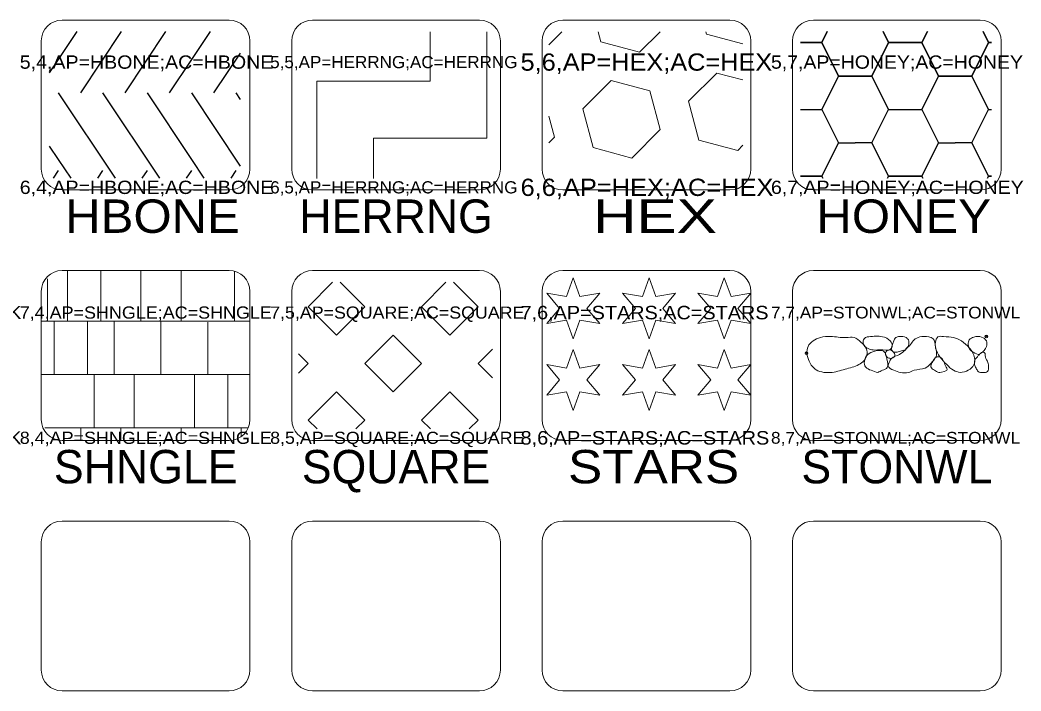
# Model space of a CAD drawing. Extents: x 95935 to 95946.4, y 95971.2 to 95974.7.
# Drawn here: x 95936.835 to 95939.233, y 95971.925 to 95973.532 of the extents above; entities that cross this region are included whole.
import ezdxf
from ezdxf.enums import TextEntityAlignment as Align

# ---------------------------------------------------------------- set-up
doc = ezdxf.new("R2010")
doc.units = 0
doc.header["$LTSCALE"] = 0.013
doc.header["$PDMODE"] = 32
doc.header["$PDSIZE"] = 0.0065
for name, color, linetype, lineweight in [('1', 7, 'Continuous', 13), ('6', 7, 'Continuous', 13), ('63', 7, 'Continuous', 13)]:
    doc.layers.add(name, color=color, linetype=linetype, lineweight=lineweight)
doc.layers.add('20', color=7, linetype='Continuous')

msp = doc.modelspace()

# ---------------------------------------------------------------- linework, layer by layer
at = {"layer": '1'}
for p, q in [((95936.9357, 95973.5318), (95937.3357, 95973.5318)), ((95937.5357, 95973.5318), (95937.9357, 95973.5318)), ((95938.1357, 95973.5318), (95938.5357, 95973.5318)), ((95938.7357, 95973.5318), (95939.1357, 95973.5318)), ((95936.8857, 95973.1747), (95936.8857, 95973.4818)), ((95937.3857, 95973.4818), (95937.3857, 95973.1747)), ((95937.4857, 95973.1747), (95937.4857, 95973.4818)), ((95937.9857, 95973.4818), (95937.9857, 95973.1747)), ((95938.0857, 95973.1747), (95938.0857, 95973.4818)), ((95938.5857, 95973.4818), (95938.5857, 95973.1747)), ((95938.6857, 95973.1747), (95938.6857, 95973.4818)), ((95939.1857, 95973.4818), (95939.1857, 95973.1747)), ((95937.3357, 95973.1247), (95936.9357, 95973.1247)), ((95937.9357, 95973.1247), (95937.5357, 95973.1247)), ((95938.5357, 95973.1247), (95938.1357, 95973.1247)), ((95939.1357, 95973.1247), (95938.7357, 95973.1247)), ((95936.9357, 95972.9318), (95937.3357, 95972.9318)), ((95937.5357, 95972.9318), (95937.9357, 95972.9318)), ((95938.1357, 95972.9318), (95938.5357, 95972.9318)), ((95938.7357, 95972.9318), (95939.1357, 95972.9318)), ((95936.8857, 95972.5747), (95936.8857, 95972.8818)), ((95937.3857, 95972.8818), (95937.3857, 95972.5747)), ((95937.4857, 95972.5747), (95937.4857, 95972.8818)), ((95937.9857, 95972.8818), (95937.9857, 95972.5747)), ((95938.0857, 95972.5747), (95938.0857, 95972.8818)), ((95938.5857, 95972.8818), (95938.5857, 95972.5747)), ((95938.6857, 95972.5747), (95938.6857, 95972.8818)), ((95939.1857, 95972.8818), (95939.1857, 95972.5747)), ((95937.3357, 95972.5247), (95936.9357, 95972.5247)), ((95937.9357, 95972.5247), (95937.5357, 95972.5247)), ((95938.5357, 95972.5247), (95938.1357, 95972.5247)), ((95939.1357, 95972.5247), (95938.7357, 95972.5247)), ((95936.9357, 95972.3318), (95937.3357, 95972.3318)), ((95937.5357, 95972.3318), (95937.9357, 95972.3318)), ((95938.1357, 95972.3318), (95938.5357, 95972.3318)), ((95938.7357, 95972.3318), (95939.1357, 95972.3318)), ((95936.8857, 95971.9747), (95936.8857, 95972.2818)), ((95937.3857, 95972.2818), (95937.3857, 95971.9747)), ((95937.4857, 95971.9747), (95937.4857, 95972.2818)), ((95937.9857, 95972.2818), (95937.9857, 95971.9747)), ((95938.0857, 95971.9747), (95938.0857, 95972.2818)), ((95938.5857, 95972.2818), (95938.5857, 95971.9747)), ((95938.6857, 95971.9747), (95938.6857, 95972.2818)), ((95939.1857, 95972.2818), (95939.1857, 95971.9747)), ((95937.3357, 95971.9247), (95936.9357, 95971.9247)), ((95937.9357, 95971.9247), (95937.5357, 95971.9247)), ((95938.5357, 95971.9247), (95938.1357, 95971.9247)), ((95939.1357, 95971.9247), (95938.7357, 95971.9247))]:
    msp.add_line(p, q, dxfattribs=at)
for centre, start, end in [((95936.9357, 95973.4818), 90, 180), ((95937.3357, 95973.4818), 0, 90), ((95937.5357, 95973.4818), 90, 180), ((95937.9357, 95973.4818), 0, 90), ((95938.1357, 95973.4818), 90, 180), ((95938.5357, 95973.4818), 0, 90), ((95938.7357, 95973.4818), 90, 180), ((95939.1357, 95973.4818), 0, 90), ((95936.9357, 95973.1747), 180, 270), ((95937.3357, 95973.1747), 270, 0), ((95937.5357, 95973.1747), 180, 270), ((95937.9357, 95973.1747), 270, 0), ((95938.1357, 95973.1747), 180, 270), ((95938.5357, 95973.1747), 270, 0), ((95938.7357, 95973.1747), 180, 270), ((95939.1357, 95973.1747), 270, 0), ((95936.9357, 95972.8818), 90, 180), ((95937.3357, 95972.8818), 0, 90), ((95937.5357, 95972.8818), 90, 180), ((95937.9357, 95972.8818), 0, 90), ((95938.1357, 95972.8818), 90, 180), ((95938.5357, 95972.8818), 0, 90), ((95938.7357, 95972.8818), 90, 180), ((95939.1357, 95972.8818), 0, 90), ((95936.9357, 95972.5747), 180, 270), ((95937.3357, 95972.5747), 270, 0), ((95937.5357, 95972.5747), 180, 270), ((95937.9357, 95972.5747), 270, 0), ((95938.1357, 95972.5747), 180, 270), ((95938.5357, 95972.5747), 270, 0), ((95938.7357, 95972.5747), 180, 270), ((95939.1357, 95972.5747), 270, 0), ((95936.9357, 95972.2818), 90, 180), ((95937.3357, 95972.2818), 0, 90), ((95937.5357, 95972.2818), 90, 180), ((95937.9357, 95972.2818), 0, 90), ((95938.1357, 95972.2818), 90, 180), ((95938.5357, 95972.2818), 0, 90), ((95938.7357, 95972.2818), 90, 180), ((95939.1357, 95972.2818), 0, 90), ((95936.9357, 95971.9747), 180, 270), ((95937.3357, 95971.9747), 270, 0), ((95937.5357, 95971.9747), 180, 270), ((95937.9357, 95971.9747), 270, 0), ((95938.1357, 95971.9747), 180, 270), ((95938.5357, 95971.9747), 270, 0), ((95938.7357, 95971.9747), 180, 270), ((95939.1357, 95971.9747), 270, 0)]:
    msp.add_arc(centre, 0.05, start, end, dxfattribs=at)
at = {"layer": '6', "lineweight": 25}
for p, q in [((95936.9708, 95973.504), (95936.9262, 95973.4371)), ((95937.0772, 95973.504), (95936.9794, 95973.3573)), ((95937.1836, 95973.504), (95937.0858, 95973.3573)), ((95937.29, 95973.504), (95937.2454, 95973.4371)), ((95939.1557, 95973.4777), (95939.1622, 95973.4777)), ((95936.9262, 95973.4371), (95936.9048, 95973.405)), ((95937.2454, 95973.4371), (95937.1922, 95973.3573)), ((95937.3622, 95973.4527), (95937.2986, 95973.3573)), ((95938.7957, 95973.3977), (95938.8357, 95973.3977)), ((95939.0357, 95973.3977), (95939.0757, 95973.3977)), ((95936.9262, 95973.3573), (95937.0626, 95973.1527)), ((95937.0326, 95973.3573), (95937.169, 95973.1527)), ((95937.139, 95973.3573), (95937.2454, 95973.1977)), ((95937.2454, 95973.3573), (95937.3622, 95973.1821)), ((95937.3518, 95973.3573), (95937.3622, 95973.3417)), ((95939.1557, 95973.3177), (95939.1622, 95973.3177)), ((95938.7957, 95973.2377), (95938.8357, 95973.2377)), ((95938.8757, 95973.2377), (95938.8357, 95973.2377)), ((95938.8757, 95973.2377), (95938.9157, 95973.1577)), ((95939.0357, 95973.2377), (95939.0757, 95973.2377)), ((95939.1157, 95973.2377), (95939.0757, 95973.2377)), ((95939.1157, 95973.2377), (95939.1557, 95973.1577)), ((95936.9048, 95973.2298), (95936.9262, 95973.1977)), ((95936.9262, 95973.1977), (95936.9562, 95973.1527)), ((95937.2454, 95973.1977), (95937.2754, 95973.1527)), ((95936.9262, 95973.1711), (95936.9139, 95973.1527)), ((95937.0326, 95973.1711), (95937.0203, 95973.1527)), ((95937.139, 95973.1711), (95937.1267, 95973.1527)), ((95937.2454, 95973.1711), (95937.2331, 95973.1527)), ((95937.3518, 95973.1711), (95937.3395, 95973.1527)), ((95939.1557, 95973.1577), (95939.1622, 95973.1577))]:
    msp.add_line(p, q, dxfattribs=at)
at = {"layer": '6'}
for p, q in [((95937.8175, 95973.385), (95937.8175, 95973.5038)), ((95937.9532, 95973.2492), (95937.9532, 95973.5038)), ((95938.1021, 95973.4726), (95938.1333, 95973.5038)), ((95938.22, 95973.5038), (95938.2265, 95973.4795)), ((95938.3192, 95973.4546), (95938.3684, 95973.5038)), ((95938.4782, 95973.5038), (95938.4798, 95973.4977)), ((95938.3192, 95973.4546), (95938.2265, 95973.4795)), ((95938.5667, 95973.4744), (95938.4798, 95973.4977)), ((95937.5459, 95973.385), (95937.8175, 95973.385)), ((95937.5459, 95973.1523), (95937.5459, 95973.385)), ((95938.1835, 95973.3189), (95938.2513, 95973.3867)), ((95938.3441, 95973.3619), (95938.2513, 95973.3867)), ((95938.4368, 95973.3371), (95938.5047, 95973.4049)), ((95938.5667, 95973.3883), (95938.5047, 95973.4049)), ((95938.3441, 95973.3619), (95938.3689, 95973.2692)), ((95938.4368, 95973.3371), (95938.4616, 95973.2443)), ((95938.1835, 95973.3189), (95938.2083, 95973.2261)), ((95938.1021, 95973.3013), (95938.1156, 95973.251)), ((95938.301, 95973.2013), (95938.3689, 95973.2692)), ((95937.6817, 95973.2492), (95937.9532, 95973.2492)), ((95937.6817, 95973.1523), (95937.6817, 95973.2492)), ((95938.1021, 95973.2375), (95938.1156, 95973.251)), ((95938.5544, 95973.2195), (95938.4616, 95973.2443)), ((95938.301, 95973.2013), (95938.2083, 95973.2261)), ((95938.5544, 95973.2195), (95938.5667, 95973.2318)), ((95936.9485, 95972.8106), (95936.9485, 95972.9318)), ((95937.0285, 95972.8106), (95937.0285, 95972.9318)), ((95937.1245, 95972.9318), (95937.1245, 95972.8106)), ((95937.2205, 95972.9318), (95937.2205, 95972.8106)), ((95937.3485, 95972.8106), (95937.3485, 95972.9293)), ((95936.9005, 95972.8106), (95936.9005, 95972.9119)), ((95936.8857, 95972.8106), (95937.3857, 95972.8106)), ((95936.9165, 95972.8106), (95936.9165, 95972.6826)), ((95936.9965, 95972.8106), (95936.9965, 95972.6826)), ((95937.0605, 95972.8106), (95937.0605, 95972.6826)), ((95937.1725, 95972.8106), (95937.1725, 95972.6826)), ((95937.2845, 95972.8084), (95937.2845, 95972.6826)), ((95936.8857, 95972.6826), (95937.3857, 95972.6826)), ((95937.0125, 95972.6826), (95937.0125, 95972.5546)), ((95937.1085, 95972.6826), (95937.1085, 95972.5546)), ((95937.2525, 95972.6826), (95937.2525, 95972.5546)), ((95937.3325, 95972.6826), (95937.3325, 95972.5546)), ((95936.894, 95972.5546), (95937.3812, 95972.5546)), ((95936.9805, 95972.5546), (95936.9805, 95972.5247)), ((95937.0765, 95972.5546), (95937.0765, 95972.5247)), ((95937.2205, 95972.5546), (95937.2205, 95972.5247)), ((95937.3645, 95972.5546), (95937.3645, 95972.5349))]:
    msp.add_line(p, q, dxfattribs=at)
at = {"layer": '6', "lineweight": 25}
for points in [[(95938.7048, 95973.4777), (95938.7557, 95973.4777), (95938.7689, 95973.504)], [(95938.7689, 95973.504), (95938.7557, 95973.4777), (95938.7957, 95973.3977)], [(95938.8357, 95973.3977), (95938.8757, 95973.3977), (95938.9157, 95973.4777), (95938.9026, 95973.504), (95938.9157, 95973.4777)], [(95938.9157, 95973.4777), (95938.9957, 95973.4777), (95939.0089, 95973.504)], [(95939.0089, 95973.504), (95938.9957, 95973.4777), (95939.0357, 95973.3977)], [(95939.0757, 95973.3977), (95939.1157, 95973.3977), (95939.1557, 95973.4777), (95939.1426, 95973.504), (95939.1557, 95973.4777)], [(95938.7048, 95973.3177), (95938.7557, 95973.3177), (95938.7957, 95973.3977), (95938.7557, 95973.4777), (95938.7048, 95973.4777)], [(95939.1622, 95973.4777), (95939.1557, 95973.4777), (95939.1157, 95973.3977), (95939.1557, 95973.3177)], [(95938.8357, 95973.3977), (95938.7957, 95973.3977), (95938.7557, 95973.3177), (95938.7957, 95973.2377)], [(95938.8757, 95973.2377), (95938.9157, 95973.3177), (95938.8757, 95973.3977), (95938.8357, 95973.3977)], [(95939.0757, 95973.3977), (95939.0357, 95973.3977), (95938.9957, 95973.3177), (95939.0357, 95973.2377)], [(95939.1157, 95973.2377), (95939.1557, 95973.3177), (95939.1157, 95973.3977), (95939.0757, 95973.3977)], [(95938.7048, 95973.1577), (95938.7557, 95973.1577), (95938.7957, 95973.2377)], [(95938.7957, 95973.2377), (95938.7557, 95973.1577), (95938.7582, 95973.1527)], [(95938.9132, 95973.1527), (95938.9157, 95973.1577), (95938.8757, 95973.2377)], [(95938.9157, 95973.1577), (95938.9957, 95973.1577), (95939.0357, 95973.2377)], [(95939.0357, 95973.2377), (95938.9957, 95973.1577), (95938.9982, 95973.1527)], [(95939.1532, 95973.1527), (95939.1557, 95973.1577), (95939.1157, 95973.2377)], [(95938.7582, 95973.1527), (95938.7557, 95973.1577), (95938.7048, 95973.1577)], [(95938.9982, 95973.1527), (95938.9957, 95973.1577), (95938.9157, 95973.1577), (95938.9132, 95973.1527)], [(95939.1622, 95973.1577), (95939.1557, 95973.1577), (95939.1532, 95973.1527)]]:
    msp.add_lwpolyline(points, dxfattribs=at)
msp.add_lwpolyline([(95938.9157, 95973.3177), (95938.9957, 95973.3177), (95939.0357, 95973.3977), (95938.9957, 95973.4777), (95938.9157, 95973.4777), (95938.8757, 95973.3977)], close=True, dxfattribs=at)
at = {"layer": '6'}
for points in [[(95937.5838, 95972.9038), (95937.5252, 95972.8451), (95937.593, 95972.7772)], [(95937.593, 95972.7772), (95937.6609, 95972.8451), (95937.6022, 95972.9038)], [(95937.8554, 95972.9038), (95937.7967, 95972.8451), (95937.8646, 95972.7772)], [(95937.8646, 95972.7772), (95937.9324, 95972.8451), (95937.8738, 95972.9038)], [(95937.9667, 95972.7436), (95937.9324, 95972.7094), (95937.9667, 95972.6751)], [(95937.5021, 95972.6863), (95937.5252, 95972.7094), (95937.5021, 95972.7325)], [(95937.6396, 95972.5523), (95937.6609, 95972.5736), (95937.593, 95972.6415), (95937.5252, 95972.5736), (95937.5465, 95972.5523)], [(95937.9111, 95972.5523), (95937.9324, 95972.5736), (95937.8646, 95972.6415), (95937.7967, 95972.5736), (95937.818, 95972.5523)]]:
    msp.add_lwpolyline(points, dxfattribs=at)
for points in [[(95938.0968, 95972.8779), (95938.144, 95972.8694), (95938.1603, 95972.9146), (95938.1765, 95972.8694), (95938.2238, 95972.8779), (95938.1928, 95972.8412), (95938.2238, 95972.8045), (95938.1765, 95972.813), (95938.1603, 95972.7678), (95938.144, 95972.813), (95938.0968, 95972.8045), (95938.1278, 95972.8412)], [(95938.2787, 95972.8779), (95938.3259, 95972.8694), (95938.3422, 95972.9146), (95938.3584, 95972.8694), (95938.4057, 95972.8779), (95938.3747, 95972.8412), (95938.4057, 95972.8045), (95938.3584, 95972.813), (95938.3422, 95972.7678), (95938.3259, 95972.813), (95938.2787, 95972.8045), (95938.3097, 95972.8412)], [(95938.4588, 95972.8779), (95938.506, 95972.8694), (95938.5223, 95972.9146), (95938.5385, 95972.8694), (95938.5858, 95972.8779), (95938.5548, 95972.8412), (95938.5858, 95972.8045), (95938.5385, 95972.813), (95938.5223, 95972.7678), (95938.506, 95972.813), (95938.4588, 95972.8045), (95938.4898, 95972.8412)], [(95937.7288, 95972.6415), (95937.7967, 95972.7094), (95937.7288, 95972.7772), (95937.6609, 95972.7094)], [(95938.0968, 95972.7063), (95938.144, 95972.6978), (95938.1603, 95972.743), (95938.1765, 95972.6978), (95938.2238, 95972.7063), (95938.1928, 95972.6696), (95938.2238, 95972.6329), (95938.1765, 95972.6414), (95938.1603, 95972.5962), (95938.144, 95972.6414), (95938.0968, 95972.6329), (95938.1278, 95972.6696)], [(95938.2787, 95972.7063), (95938.3259, 95972.6978), (95938.3422, 95972.743), (95938.3584, 95972.6978), (95938.4057, 95972.7063), (95938.3747, 95972.6696), (95938.4057, 95972.6329), (95938.3584, 95972.6414), (95938.3422, 95972.5962), (95938.3259, 95972.6414), (95938.2787, 95972.6329), (95938.3097, 95972.6696)], [(95938.4588, 95972.7063), (95938.506, 95972.6978), (95938.5223, 95972.743), (95938.5385, 95972.6978), (95938.5858, 95972.7063), (95938.5548, 95972.6696), (95938.5858, 95972.6329), (95938.5385, 95972.6414), (95938.5223, 95972.5962), (95938.506, 95972.6414), (95938.4588, 95972.6329), (95938.4898, 95972.6696)]]:
    msp.add_lwpolyline(points, close=True, dxfattribs=at)
for points in [[(95938.7604, 95972.6877), (95938.7426, 95972.6939), (95938.7255, 95972.7144), (95938.723, 95972.7499), (95938.7525, 95972.7712), (95938.7767, 95972.7738), (95938.8146, 95972.7712), (95938.8335, 95972.7712), (95938.8498, 95972.7603), (95938.8633, 95972.7439), (95938.8574, 95972.7164), (95938.8445, 95972.7063), (95938.8118, 95972.6953), (95938.7767, 95972.6874), (95938.7604, 95972.6877)], [(95938.8824, 95972.7414), (95938.8686, 95972.7439), (95938.8568, 95972.7532), (95938.8551, 95972.7631), (95938.8608, 95972.7712), (95938.8689, 95972.7732), (95938.901, 95972.7732), (95938.9201, 95972.7631), (95938.9243, 95972.7501), (95938.9184, 95972.7417), (95938.9094, 95972.7414), (95938.8824, 95972.7414)], [(95938.9446, 95972.6874), (95938.9283, 95972.6928), (95938.9148, 95972.7034), (95938.9173, 95972.7116), (95938.9232, 95972.7214), (95938.9418, 95972.7304), (95938.9553, 95972.7414), (95938.9688, 95972.7549), (95938.9769, 95972.7656), (95938.9907, 95972.7726), (95939.0121, 95972.7729), (95939.023, 95972.7684), (95939.0284, 95972.7496), (95939.0304, 95972.7282), (95939.0171, 95972.7091), (95939.0039, 95972.6981), (95938.9769, 95972.6928), (95938.9634, 95972.6874), (95938.9446, 95972.6874)], [(95938.9553, 95972.7414), (95938.9446, 95972.7386), (95938.9336, 95972.7361), (95938.9255, 95972.7386), (95938.9229, 95972.7439), (95938.9255, 95972.7549), (95938.9283, 95972.7631), (95938.9336, 95972.7712), (95938.9418, 95972.7738), (95938.9581, 95972.7712), (95938.9634, 95972.7656), (95938.9634, 95972.7521), (95938.9553, 95972.7414)], [(95939.0877, 95972.6874), (95939.0717, 95972.6928), (95939.0554, 95972.7063), (95939.0391, 95972.7251), (95939.0287, 95972.7451), (95939.0284, 95972.7603), (95939.0343, 95972.7729), (95939.0475, 95972.7735), (95939.0717, 95972.7712), (95939.0905, 95972.7631), (95939.1094, 95972.7468), (95939.1218, 95972.7223), (95939.1204, 95972.7063), (95939.1069, 95972.6928), (95939.0877, 95972.6874)], [(95939.131, 95972.7304), (95939.1147, 95972.7386), (95939.1069, 95972.7549), (95939.1094, 95972.7656), (95939.1206, 95972.7724), (95939.1389, 95972.7724), (95939.1502, 95972.7631), (95939.1502, 95972.7499), (95939.1364, 95972.7333), (95939.131, 95972.7304)], [(95938.8903, 95972.6874), (95938.8743, 95972.6928), (95938.8608, 95972.7009), (95938.858, 95972.7144), (95938.8661, 95972.7304), (95938.8827, 95972.7386), (95938.9038, 95972.7383), (95938.912, 95972.7198), (95938.9128, 95972.6995), (95938.9013, 95972.6928), (95938.8903, 95972.6874)], [(95938.9232, 95972.7214), (95938.9148, 95972.7226), (95938.9094, 95972.7279), (95938.9094, 95972.7361), (95938.9148, 95972.7414), (95938.9255, 95972.7386), (95938.9311, 95972.7279), (95938.9232, 95972.7214)], [(95939.1555, 95972.6953), (95939.1527, 95972.6899), (95939.142, 95972.6874), (95939.131, 95972.6899), (95939.1257, 95972.6981), (95939.1218, 95972.7063), (95939.1229, 95972.7169), (95939.131, 95972.7279), (95939.1364, 95972.7333), (95939.142, 95972.7361), (95939.1474, 95972.7333), (95939.1474, 95972.7279), (95939.1527, 95972.7144), (95939.1555, 95972.7034), (95939.1555, 95972.6953)], [(95939.0365, 95972.6874), (95939.0256, 95972.6928), (95939.0174, 95972.7009), (95939.0205, 95972.7113), (95939.0312, 95972.7248), (95939.0365, 95972.7251), (95939.0467, 95972.7164), (95939.0526, 95972.7034), (95939.0554, 95972.6928), (95939.0365, 95972.6874), (95939.0391, 95972.6874)]]:
    msp.add_spline(points, degree=3, dxfattribs=at)
for p in [(95939.1502, 95972.7738), (95938.7192, 95972.734)]:
    msp.add_point(p, dxfattribs=at)

# ---------------------------------------------------------------- texts
at = {"layer": '20'}
for s, width, p in [(' HBONE', 1.1, (95937.1359, 95973.022)), ('  HEX ', 1.35, (95938.3359, 95973.022)), (' HONEY', 1.1, (95938.9358, 95973.022)), (' STARS', 1.15, (95938.3358, 95972.422))]:
    msp.add_text(s, height=0.08, dxfattribs=dict(at, width=width)).set_placement(p, align=Align.CENTER)
for s, p in [('HERRNG', (95937.7358, 95973.022)), ('SHNGLE', (95937.1358, 95972.422)), ('SQUARE', (95937.7358, 95972.422)), ('STONWL', (95938.9358, 95972.422))]:
    msp.add_text(s, height=0.08, dxfattribs=at).set_placement(p, align=Align.CENTER)
at = {"layer": '63'}
for s, height, width, p in [('5,4,AP=HBONE;AC=HBONE', 0.0319, 1.1, (95936.8341, 95973.4151)), ('5,5,AP=HERRNG;AC=HERRNG', 0.0291, 1.05, (95937.4341, 95973.4165)), ('5,6,AP=HEX;AC=HEX', 0.0412, 1.1, (95938.0341, 95973.4105)), ('5,7,AP=HONEY;AC=HONEY', 0.0317, 1.1, (95938.6341, 95973.4152)), ('6,4,AP=HBONE;AC=HBONE', 0.0319, 1.1, (95936.8341, 95973.1151)), ('6,5,AP=HERRNG;AC=HERRNG', 0.0291, 1.05, (95937.4341, 95973.1165)), ('6,6,AP=HEX;AC=HEX', 0.0414, 1.1, (95938.0341, 95973.1104)), ('6,7,AP=HONEY;AC=HONEY', 0.0318, 1.1, (95938.6341, 95973.1152)), ('7,3,AP=SBRICK;AC=SBRICK', 0.0309, 1.1, (95936.2341, 95972.8156)), ('7,4,AP=SHNGLE;AC=SHNGLE', 0.0292, 1.1, (95936.8341, 95972.8165)), ('7,5,AP=SQUARE;AC=SQUARE', 0.029, 1.1, (95937.4341, 95972.8166)), ('7,6,AP=STARS;AC=STARS', 0.0323, 1.1, (95938.0341, 95972.8149)), ('7,7,AP=STONWL;AC=STONWL', 0.0282, 1.1, (95938.6341, 95972.817)), ('8,3,AP=SBRICK;AC=SBRICK', 0.0309, 1.1, (95936.2341, 95972.5156)), ('8,4,AP=SHNGLE;AC=SHNGLE', 0.0292, 1.1, (95936.8341, 95972.5165)), ('8,5,AP=SQUARE;AC=SQUARE', 0.029, 1.1, (95937.4341, 95972.5166)), ('8,6,AP=STARS;AC=STARS', 0.0324, 1.1, (95938.0341, 95972.5149)), ('8,7,AP=STONWL;AC=STONWL', 0.0282, 1.1, (95938.6341, 95972.517))]:
    msp.add_text(s, height=height, dxfattribs=dict(at, width=width)).set_placement(p)

doc.saveas('drawing.dxf')
